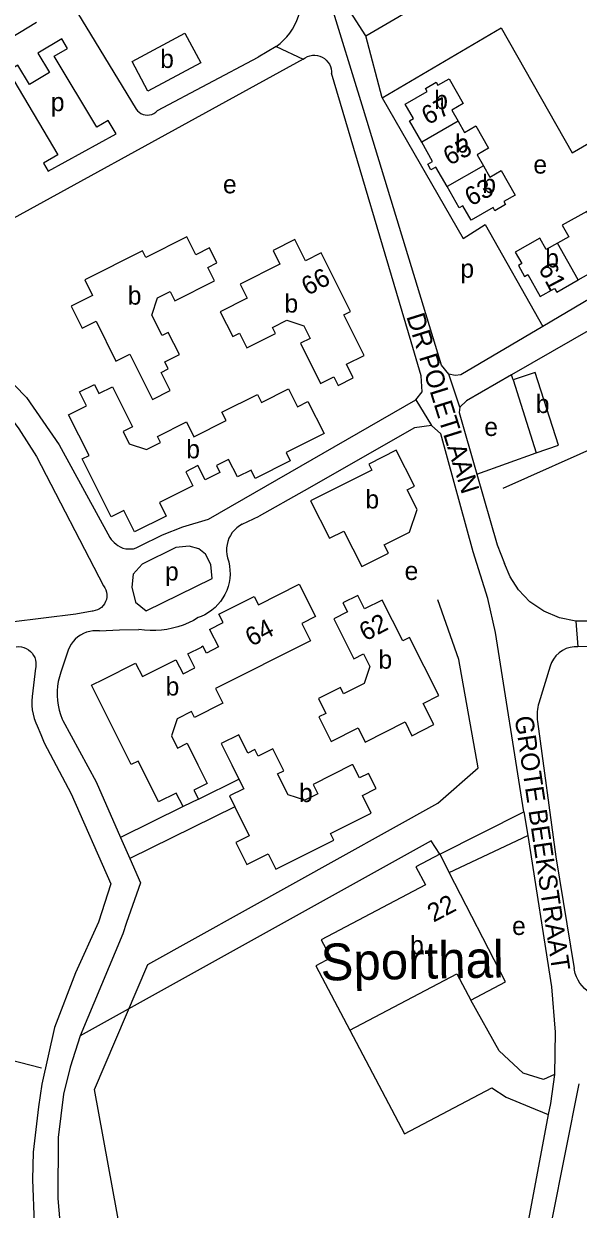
# Model space of a CAD drawing. Extents: x 158142 to 159655, y 385262 to 387204.
# Drawn here: x 158722.6 to 158843.1, y 386403.5 to 386661 of the extents above; entities that cross this region are included whole.
import ezdxf

# ---------------------------------------------------------------- set-up
doc = ezdxf.new("R2010")
doc.units = 0
for name, color, linetype in [('BLT_Basislijn', 7, 'Continuous'), ('BLT_Bebouwing', 7, 'Continuous'), ('BLT_Bebouwing_beschrifting', 7, 'Continuous'), ('BLT_Centroide', 7, 'Continuous'), ('BLT_Huisnummer', 7, 'Continuous'), ('BLT_Huisnummer_ tussenligend', 7, 'Continuous'), ('BLT_Onderverdeling_panden', 7, 'Continuous'), ('BLT_Straatnaam_verkleind', 7, 'Continuous'), ('BLT_Vlakafsluiter', 7, 'Continuous')]:
    doc.layers.add(name, color=color, linetype=linetype)

msp = doc.modelspace()

# ---------------------------------------------------------------- linework, layer by layer
at = {"layer": 'BLT_Basislijn'}
for p, q in [((158796.96, 386658.41), (158786.24, 386675.16)), ((158728.49, 386672.91), (158747.01, 386642.5)), ((158796.96, 386658.41), (158813.21, 386667.91)), ((158800.5, 386644.91), (158796.96, 386658.41)), ((158751.66, 386642.15), (158773.56, 386653.78)), ((158777.49, 386656.07), (158773.56, 386653.78)), ((158806.78, 386591.92), (158789.49, 386650.31)), ((158828.98, 386583.64), (158828.64, 386584.76)), ((158826.78, 386560.1), (158854.55, 386572.55)), ((158821.11, 386563.19), (158833.99, 386567.84)), ((158770.06, 386552.33), (158773.75, 386554.02)), ((158732.06, 386524.48), (158730.67, 386520.15)), ((158725.15, 386521.03), (158724.4, 386514.88)), ((158725.48, 386508.52), (158726.28, 386506.62)), ((158760.54, 386492.61), (158769.34, 386496.95)), ((158757.24, 386490.95), (158743.6, 386484.26)), ((158768.47, 386490.9), (158745.62, 386479.68)), ((158813.04, 386480.63), (158831.27, 386489.83)), ((158831.27, 386489.83), (158832.15, 386484.68)), ((158743.6, 386484.26), (158745.62, 386479.68)), ((158811.12, 386483.52), (158734.85, 386441.17)), ((158710.88, 386438.27), (158726.42, 386434.18))]:
    msp.add_line(p, q, dxfattribs=at)
for points in [[(158800.5, 386644.91), (158826.35, 386660.11), (158841.79, 386632.99), (158934.18, 386686.67), (158951.94, 386658.76)], [(158777.49, 386656.07), (158778.31, 386656.71), (158779.07, 386657.42), (158779.78, 386658.18), (158780.43, 386658.99), (158781.01, 386659.85), (158781.52, 386660.75), (158781.97, 386661.69), (158782.34, 386662.66), (158782.64, 386663.66), (158782.85, 386664.68), (158782.99, 386665.71), (158783.05, 386666.74), (158783.03, 386667.78), (158782.93, 386668.82), (158782.75, 386669.84), (158782.49, 386670.85), (158782.16, 386671.83), (158781.75, 386672.79), (158781.27, 386673.71), (158780.72, 386674.59), (158780.64, 386674.69)], [(158796.42, 386642.36), (158789, 386666.64)], [(158783.34, 386653.33), (158783.79, 386653.65), (158784.28, 386653.89), (158784.8, 386654.07), (158785.34, 386654.16), (158785.89, 386654.18), (158786.43, 386654.12), (158786.96, 386653.97), (158787.47, 386653.76), (158787.93, 386653.47), (158788.35, 386653.12), (158788.72, 386652.71), (158789.02, 386652.25), (158789.25, 386651.75), (158789.41, 386651.23), (158789.48, 386650.68), (158789.49, 386650.31)], [(158783.34, 386653.33), (158700.4, 386607.86), (158696.69, 386605.76)], [(158800.5, 386644.91), (158818.12, 386614.39), (158822.89, 386617.39), (158835.4, 386595.28)], [(158747.01, 386642.5), (158747.31, 386642.11), (158747.67, 386641.79), (158748.07, 386641.52), (158748.52, 386641.33), (158748.99, 386641.21), (158749.47, 386641.17), (158749.95, 386641.21), (158750.42, 386641.32), (158750.86, 386641.52), (158751.27, 386641.78), (158751.66, 386642.15)], [(158815.02, 386584.89), (158813.4, 386586.86), (158796.42, 386642.36)], [(158925.01, 386641.49), (158915.91, 386635.65), (158913.62, 386633.64), (158910.28, 386627.76), (158908.07, 386625.82), (158897.31, 386623.34), (158889.29, 386621.08), (158876.15, 386616.73), (158865.98, 386612.5), (158856.4, 386607.67), (158835.4, 386595.28)], [(158943.04, 386622.77), (158928.51, 386622.6), (158913, 386620.87), (158891.33, 386615.63), (158878.55, 386611.27), (158868.25, 386606.92), (158859.58, 386602.5), (158828.64, 386584.76)], [(158696.08, 386598.01), (158712.54, 386589.37), (158718.01, 386585.14), (158723.17, 386579.86), (158730.26, 386569.56), (158741.33, 386549.4)], [(158835.4, 386595.28), (158817.63, 386584.79), (158816.36, 386584.63), (158815.02, 386584.89)], [(158694.85, 386593.18), (158708.52, 386585.9), (158712.94, 386582.4), (158718.17, 386577.51), (158721.5, 386572.99), (158725.33, 386567.01), (158739.93, 386538.93)], [(158807.85, 386579.31), (158809.18, 386581.09), (158808.98, 386584.51), (158806.78, 386591.92)], [(158828.64, 386584.76), (158818.83, 386579.14), (158817.41, 386577.76)], [(158762.73, 386553.41), (158807.85, 386579.31)], [(158817.41, 386577.76), (158817.25, 386576.55), (158821.11, 386563.19)], [(158811.26, 386573.73), (158807.52, 386573.23), (158783.57, 386559.59), (158773.75, 386554.02)], [(158831.27, 386489.83), (158825.12, 386528.81), (158823.48, 386536.16), (158820.27, 386546.34), (158813.29, 386571.91), (158811.26, 386573.73)], [(158821.11, 386563.19), (158825.53, 386547.86), (158827.13, 386543.77)], [(158741.33, 386549.4), (158741.6, 386549), (158741.86, 386548.67), (158742.24, 386548.31), (158742.65, 386547.94), (158743.04, 386547.66), (158743.56, 386547.4), (158744.15, 386547.13), (158744.8, 386546.96), (158745.24, 386546.94), (158745.86, 386546.94), (158746.42, 386546.98), (158747.01, 386547.15), (158747.78, 386547.54), (158752.78, 386549.97), (158757.18, 386551.7), (158762.73, 386553.41)], [(158770.06, 386552.33), (158769.45, 386551.96), (158768.88, 386551.53), (158768.37, 386551.03), (158767.91, 386550.48), (158767.52, 386549.88), (158767.2, 386549.24), (158766.95, 386548.58), (158766.78, 386547.88), (158766.68, 386547.17), (158766.67, 386546.46), (158766.73, 386545.75), (158766.9, 386544.98)], [(158766.9, 386544.98), (158767.15, 386544.11), (158767.32, 386543.22), (158767.42, 386542.32), (158767.43, 386541.42), (158767.37, 386540.52), (158767.22, 386539.62), (158767, 386538.75), (158766.7, 386537.89), (158766.33, 386537.07), (158765.88, 386536.28), (158765.37, 386535.54), (158764.79, 386534.84), (158764.16, 386534.2), (158763.47, 386533.61), (158762.73, 386533.09), (158761.95, 386532.64), (158761.13, 386532.26), (158760.53, 386532.03)], [(158842.64, 386531.24), (158839.05, 386531.95), (158835.64, 386533.39), (158832.63, 386535.46), (158830.17, 386538.02), (158828.34, 386540.85), (158827.13, 386543.77)], [(158739.93, 386538.93), (158740.22, 386538.5), (158740.44, 386538.03), (158740.59, 386537.53), (158740.66, 386537.02), (158740.65, 386536.49), (158740.56, 386535.98), (158740.39, 386535.49), (158740.15, 386535.03), (158739.84, 386534.61), (158739.47, 386534.24), (158739.05, 386533.93), (158738.58, 386533.7), (158738.09, 386533.53), (158737.57, 386533.44), (158737.45, 386533.43)], [(158757.54, 386322.67), (158737.93, 386429.5), (158749.55, 386456.64), (158812.62, 386491.7), (158821.39, 386499.37), (158817.14, 386522.92), (158812.61, 386535.9)], [(158737.45, 386533.43), (158733.92, 386532.74), (158705.73, 386529.3)], [(158852.43, 386533.1), (158849.49, 386531.93), (158846.18, 386531.26), (158842.64, 386531.24)], [(158760.53, 386532.03), (158759.47, 386531.42), (158758.38, 386530.88), (158757.25, 386530.4), (158756.1, 386530.01), (158754.92, 386529.69), (158753.72, 386529.45), (158752.51, 386529.29), (158751.29, 386529.2), (158750.07, 386529.2), (158748.85, 386529.28), (158747.63, 386529.44)], [(158739.07, 386529.12), (158738.35, 386529.17), (158737.63, 386529.13), (158736.92, 386529.02), (158736.22, 386528.83), (158735.56, 386528.57), (158734.92, 386528.23), (158734.33, 386527.82), (158733.78, 386527.35), (158733.29, 386526.82), (158732.87, 386526.24), (158732.5, 386525.62), (158732.21, 386524.96), (158732.06, 386524.48)], [(158739.07, 386529.12), (158743.38, 386529.34), (158747.63, 386529.44)], [(158720.96, 386525.69), (158721.51, 386525.71), (158722.06, 386525.66), (158722.6, 386525.52), (158723.11, 386525.31), (158723.59, 386525.03), (158724.02, 386524.68), (158724.4, 386524.28), (158724.71, 386523.82), (158724.96, 386523.33), (158725.13, 386522.8), (158725.23, 386522.25), (158725.24, 386521.7), (158725.18, 386521.15), (158725.15, 386521.03)], [(158843.07, 386525.7), (158842.23, 386525.68), (158841.37, 386525.54), (158840.52, 386525.27), (158839.7, 386524.87), (158838.95, 386524.35), (158838.29, 386523.72), (158837.74, 386523.01), (158837.32, 386522.25), (158837.02, 386521.46)], [(158852.68, 386527.24), (158852.11, 386527), (158849.15, 386526.17), (158846.11, 386525.73), (158843.07, 386525.7)], [(158730.67, 386520.15), (158730.35, 386519.16), (158730.1, 386518.14), (158729.93, 386517.11), (158729.84, 386516.08), (158729.83, 386515.03), (158729.9, 386513.99), (158730.05, 386512.96), (158730.28, 386511.94), (158730.58, 386510.95), (158730.96, 386509.98), (158731.09, 386509.7)], [(158837.02, 386521.46), (158834.54, 386513.4)], [(158724.4, 386514.88), (158724.33, 386513.91), (158724.34, 386512.95), (158724.44, 386511.98), (158724.61, 386511.03), (158724.86, 386510.09), (158725.18, 386509.18), (158725.48, 386508.52)], [(158834.54, 386513.4), (158834.43, 386512.97), (158834.35, 386512.53), (158834.27, 386512.09), (158834.22, 386511.65), (158834.19, 386511.21), (158834.17, 386510.76), (158834.18, 386510.32), (158834.2, 386509.88), (158834.24, 386509.43)], [(158731.09, 386509.7), (158738.3, 386496.31), (158743.6, 386484.26)], [(158834.24, 386509.43), (158838.29, 386480.03), (158842.24, 386455.77)], [(158726.28, 386506.62), (158727, 386504.84), (158732.89, 386493.7), (158741.5, 386474.16), (158738.85, 386465.87), (158733.82, 386454.83), (158729.3, 386442.97), (158726.5, 386430.65), (158725.78, 386425.75), (158724.61, 386415.86), (158724.5, 386409.95), (158724.83, 386400.43), (158727.71, 386375.28), (158734.92, 386340.45), (158744.35, 386298.39), (158748.73, 386281.78), (158755.35, 386261.93), (158761.86, 386241.17)], [(158815.08, 386476.68), (158832.15, 386484.68)], [(158832.15, 386484.68), (158837.28, 386451.8), (158838.08, 386441.95), (158838, 386432.76)], [(158813.04, 386480.63), (158811.12, 386483.52)], [(158745.62, 386479.68), (158747.94, 386474.42), (158744.94, 386465.78), (158744.09, 386463.34), (158734.85, 386441.17)], [(158850.89, 386449.52), (158850.13, 386449.43), (158849.36, 386449.41), (158848.59, 386449.47), (158847.83, 386449.62), (158847.09, 386449.84), (158846.38, 386450.14), (158845.71, 386450.5), (158845.07, 386450.94), (158844.49, 386451.44), (158843.96, 386452), (158843.49, 386452.61), (158843.08, 386453.26), (158842.75, 386453.96), (158842.49, 386454.68), (158842.3, 386455.43), (158842.24, 386455.77)], [(158838, 386432.76), (158835.58, 386431.65), (158831.19, 386433.08), (158825.91, 386437.87), (158819.8, 386448.9)], [(158734.85, 386441.17), (158732.67, 386434.38), (158731.21, 386428.49), (158730.09, 386419.09), (158730.02, 386405.84), (158731.42, 386388.95), (158733.76, 386371.24), (158747.12, 386306.2), (158753.2, 386284.87), (158764.97, 386248.15)], [(158793.47, 386442.36), (158805.34, 386419.87), (158824.34, 386429.9), (158827.47, 386427.84), (158832.5, 386425.75), (158836.62, 386424.04)], [(158838, 386432.76), (158837.08, 386426.49), (158836.62, 386424.04)], [(158843.29, 386430.77), (158837.33, 386400.92), (158837.2, 386395.94), (158837.65, 386388.99), (158838.18, 386387.27)], [(158836.62, 386424.04), (158831.91, 386398.97), (158831.88, 386390.19)]]:
    msp.add_lwpolyline(points, dxfattribs=at)
for points in [[(158730.85, 386657.75), (158725.64, 386654.65), (158728.16, 386650.42), (158723.8, 386647.82), (158721.29, 386652.03), (158716.07, 386648.92), (158717.32, 386646.82), (158720.43, 386648.68), (158730.02, 386632.57), (158726.88, 386630.7), (158727.87, 386629.03), (158742.68, 386637.11), (158740.94, 386640.01), (158738.48, 386638.53), (158729.22, 386653.98), (158732.1, 386655.63)], [(158755.63, 386547.24), (158748.3, 386543.59), (158746.39, 386541.47), (158746.05, 386538.63), (158746.88, 386535.38), (158749.2, 386533.52), (158763.57, 386540.53), (158763.25, 386543.55), (158762.12, 386545.77), (158760.67, 386546.93), (158758.51, 386547.5)]]:
    msp.add_lwpolyline(points, close=True, dxfattribs=at)
at = {"layer": 'BLT_Bebouwing'}
for p, q in [((158828.98, 386583.64), (158833.99, 386567.84)), ((158760.54, 386492.61), (158757.24, 386490.95)), ((158813.04, 386480.63), (158815.08, 386476.68))]:
    msp.add_line(p, q, dxfattribs=at)
for points in [[(158725.33, 386661.29), (158717.94, 386656.78), (158716.61, 386658.87), (158715.3, 386658.1), (158713.66, 386658.48), (158708.76, 386655.49), (158708.35, 386653.84), (158707.05, 386653.03), (158708.34, 386650.9)], [(158805.52, 386643.57), (158810.28, 386646.29), (158809.89, 386646.99), (158812.24, 386648.33), (158812.63, 386647.65), (158815.07, 386649.05), (158818.14, 386643.66), (158815.65, 386642.24), (158817.03, 386639.83)], [(158809.09, 386635.3), (158806.44, 386639.95), (158807.3, 386640.44), (158805.52, 386643.57)], [(158817.03, 386639.83), (158818.4, 386637.41), (158820.87, 386638.82), (158823.62, 386633.99), (158821.13, 386632.57), (158822.51, 386630.14)], [(158814.6, 386625.63), (158812.18, 386629.89), (158811.11, 386629.29), (158810.43, 386630.5), (158811.48, 386631.1), (158809.09, 386635.3)], [(158822.51, 386630.14), (158823.89, 386627.71), (158826.39, 386629.13), (158829.42, 386623.81), (158826.96, 386622.42), (158827.35, 386621.74), (158824.99, 386620.4), (158824.6, 386621.09), (158819.82, 386618.36), (158818.03, 386621.5), (158817.22, 386621.04), (158814.6, 386625.63)], [(158843.11, 386605.37), (158847.77, 386608.01), (158847.3, 386608.84), (158850.48, 386610.64), (158847.77, 386615.42), (158848.36, 386615.75), (158847.03, 386618.11), (158846.41, 386617.75), (158844.99, 386620.25), (158839.65, 386617.23), (158841.07, 386614.72), (158838.6, 386613.33)], [(158735.83, 386605.42), (158737.54, 386602.01), (158732.91, 386599.69), (158735.31, 386594.89), (158738.29, 386596.39), (158742.63, 386587.74), (158745.62, 386589.24), (158750.54, 386579.42), (158754.44, 386581.37), (158752.49, 386585.27), (158754, 386586.03), (158753.23, 386587.56), (158756.42, 386589.16), (158754, 386593.98), (158752.65, 386593.3), (158750.42, 386597.74), (158751.67, 386601.49), (158754.42, 386602.86), (158755.43, 386600.86), (158764.08, 386605.19), (158762.62, 386608.1), (158764.58, 386609.08), (158762.96, 386612.33), (158759.96, 386610.82), (158758.01, 386614.71), (158749.13, 386610.27), (158748.4, 386611.72), (158735.83, 386605.42)], [(158776.78, 386611.74), (158778.25, 386608.8), (158769.61, 386604.47), (158771.16, 386601.39), (158765.3, 386598.46), (158768.01, 386593.05), (158769.48, 386593.79), (158771.07, 386590.62), (158777.29, 386593.73), (158776.63, 386595.05), (158779.79, 386596.63), (158783.45, 386595.42), (158784.82, 386592.68), (158782.73, 386591.63), (158787.12, 386582.89), (158789.97, 386584.32), (158790.91, 386582.46), (158794.21, 386584.11), (158792.74, 386587.04), (158796.58, 386588.96), (158792.15, 386597.79), (158793.6, 386598.52), (158787.23, 386611.22), (158783.85, 386609.52), (158781.54, 386614.12), (158776.78, 386611.74)], [(158838.6, 386613.33), (158836.17, 386611.95), (158834.77, 386614.42), (158829.43, 386611.4), (158830.84, 386608.92), (158830.13, 386608.52), (158831.47, 386606.15)], [(158831.47, 386606.15), (158832.18, 386606.55), (158834.88, 386601.77), (158837.99, 386603.53), (158838.44, 386602.73), (158843.11, 386605.37)], [(158833.99, 386567.84), (158838.83, 386569.44), (158833.75, 386585.29), (158828.98, 386583.64)], [(158765.19, 386563.57), (158761.99, 386561.96), (158760.45, 386565.03), (158757.79, 386563.7), (158759.32, 386560.63), (158752.08, 386557), (158753.55, 386554.07), (158746.67, 386550.62), (158744.33, 386555.29), (158741.61, 386553.92), (158735.31, 386566.49), (158736.78, 386567.22), (158732.33, 386576.1), (158736.2, 386578.04), (158734.71, 386581.03), (158737.93, 386582.65), (158738.92, 386580.68), (158741.86, 386582.15), (158746.2, 386573.49), (158744.17, 386572.47), (158745.52, 386569.77), (158749.28, 386568.52), (158752.34, 386570.05), (158751.67, 386571.39), (158757.93, 386574.53), (158759.56, 386571.29), (158766.58, 386574.81), (158765.67, 386576.62), (158773.39, 386580.49), (158774.25, 386578.76), (158780.14, 386581.71), (158782.09, 386577.82), (158784.37, 386578.96), (158787.86, 386572), (158779.62, 386567.87), (158780.53, 386566.07), (158772.9, 386562.24), (158771.99, 386564.05), (158769.03, 386562.57), (158767.12, 386566.37), (158764.46, 386565.04), (158765.19, 386563.57)], [(158808.1, 386555.48), (158805.94, 386559.78), (158807.5, 386560.55), (158803.58, 386568.36), (158797.57, 386565.35), (158798.24, 386564.02), (158784.95, 386557.35), (158789.02, 386549.24), (158792.17, 386550.82), (158796.05, 386543.1), (158801.86, 386546.02), (158800.96, 386547.81), (158806.47, 386550.57), (158808.1, 386555.48)], [(158762.99, 386529.46), (158765.91, 386530.92), (158765, 386532.74), (158772.7, 386536.61), (158773.61, 386534.8), (158782.47, 386539.25), (158785.99, 386532.24), (158783.01, 386530.74), (158784.91, 386526.96), (158764.29, 386516.61), (158765.88, 386513.43), (158759.69, 386510.33), (158759.05, 386511.6), (158755.94, 386510.04), (158754.71, 386506.32), (158756.03, 386503.69), (158758.09, 386504.73), (158760.46, 386500), (158762.48, 386496), (158759.57, 386494.54), (158760.54, 386492.61)], [(158791.97, 386535.21), (158792.96, 386533.24), (158790, 386531.75), (158794.36, 386523.07), (158796.44, 386524.12), (158797.81, 386521.39), (158796.59, 386517.72), (158792.09, 386515.46), (158791.41, 386516.81), (158786.63, 386514.41), (158788.23, 386511.22), (158786.73, 386510.47), (158789.43, 386505.09), (158795.31, 386508.04), (158796.84, 386504.99), (158805.49, 386509.34), (158806.98, 386506.36), (158811.76, 386508.76), (158809.43, 386513.39), (158812.79, 386515.08), (158806.46, 386527.69), (158804.99, 386526.95), (158800.53, 386535.82), (158796.68, 386533.89), (158795.2, 386536.83), (158791.97, 386535.21)], [(158762.99, 386529.46), (158764.9, 386525.64), (158762.28, 386524.32), (158761.55, 386525.78), (158761.21, 386525.61)], [(158757.24, 386490.95), (158755.75, 386493.91), (158751.9, 386491.97), (158747.87, 386500), (158747.44, 386500.84), (158745.97, 386500.1), (158739.64, 386512.72), (158737.33, 386517.32), (158740.02, 386518.67), (158746.9, 386522.13), (158748.37, 386519.19), (158755.67, 386522.86), (158757.21, 386519.78), (158759.8, 386521.07), (158758.27, 386524.13), (158761.21, 386525.61)], [(158794.14, 386500), (158793.93, 386500), (158785.47, 386495.75), (158786.49, 386493.72), (158783.72, 386492.33), (158780.04, 386493.55), (158777.77, 386498.07), (158779.12, 386498.75), (158778.49, 386500), (158776.73, 386503.5), (158773.57, 386501.91), (158772.84, 386503.37), (158771.3, 386502.6), (158769.31, 386506.56), (158765.48, 386504.64), (158767.81, 386500), (158769.34, 386496.95)], [(158768.47, 386490.9), (158771.62, 386484.62), (158768.72, 386483.16), (158771.11, 386478.41), (158775.72, 386480.72), (158777.42, 386477.34), (158790.01, 386483.66), (158789.28, 386485.12), (158798.13, 386489.56), (158796.21, 386493.39), (158799.19, 386494.89), (158797.55, 386498.18), (158795.56, 386497.18), (158794.14, 386500)], [(158769.34, 386496.95), (158770.4, 386494.84), (158767.28, 386493.27), (158768.47, 386490.9)], [(158813.04, 386480.63), (158807.84, 386477.9), (158809.92, 386473.95), (158787.27, 386461.99), (158789.31, 386458.12), (158786.06, 386456.4), (158793.47, 386442.36)], [(158819.8, 386448.9), (158827.31, 386452.93), (158815.08, 386476.68)], [(158793.47, 386442.36), (158816.76, 386454.66), (158819.8, 386448.9)]]:
    msp.add_lwpolyline(points, dxfattribs=at)
msp.add_lwpolyline([(158746.15, 386652.84), (158757.6, 386658.99), (158761.05, 386652.55), (158749.58, 386646.36)], close=True, dxfattribs=at)
at = {"layer": 'BLT_Onderverdeling_panden'}
for p, q in [((158817.03, 386639.83), (158809.09, 386635.3)), ((158822.51, 386630.14), (158814.6, 386625.63)), ((158843.11, 386605.37), (158838.6, 386613.33))]:
    msp.add_line(p, q, dxfattribs=at)
at = {"layer": 'BLT_Vlakafsluiter'}
for p, q in [((158777.49, 386656.07), (158783.34, 386653.33)), ((158817.41, 386577.76), (158815.02, 386584.89)), ((158807.85, 386579.31), (158811.26, 386573.73)), ((158842.64, 386531.24), (158843.07, 386525.7))]:
    msp.add_line(p, q, dxfattribs=at)

# ---------------------------------------------------------------- texts
at = {"layer": 'BLT_Bebouwing_beschrifting'}
msp.add_text('Sporthal', height=8, rotation=1, dxfattribs=at).set_placement((158787.18, 386453.16))
at = {"layer": 'BLT_Centroide'}
for s, p in [('b', (158752.25, 386651.42)), ('b', (158811.83, 386642.48)), ('p', (158728.47, 386642.03)), ('b', (158816.36, 386633.03)), ('e', (158833.38, 386628.47)), ('b', (158822.28, 386624.25)), ('e', (158765.9, 386624.18)), ('b', (158835.97, 386608.09)), ('p', (158817.52, 386605.85)), ('b', (158745.19, 386600)), ('b', (158779.27, 386598.28)), ('b', (158833.91, 386576.45)), ('e', (158822.71, 386571.47)), ('b', (158757.92, 386566.62)), ('b', (158796.87, 386555.72)), ('p', (158753.3, 386540.07)), ('e', (158805.38, 386540.19)), ('b', (158799.7, 386520.92)), ('b', (158753.43, 386515.09)), ('b', (158782.44, 386491.94)), ('e', (158828.75, 386463.07)), ('b', (158806.59, 386458.88))]:
    msp.add_text(s, height=4, dxfattribs=at).set_placement(p)
at = {"layer": 'BLT_Huisnummer'}
for s, rotation, p in [('67', 27.8253, (158810.41, 386638.95)), ('63', 27.8253, (158819.8, 386621.29)), ('66', 27.8253, (158784.29, 386601.87)), ('61', 297.8252, (158834.37, 386607.89)), ('62', 27.8253, (158796.86, 386526.79)), ('64', 27.8253, (158772.08, 386525.64)), ('22', 27.8253, (158811.67, 386465.74))]:
    msp.add_text(s, height=4, rotation=rotation, dxfattribs=at).set_placement(p)
at = {"layer": 'BLT_Huisnummer_ tussenligend'}
msp.add_text('65', height=4, rotation=27.8253, dxfattribs=at).set_placement((158815.13, 386630.13))
at = {"layer": 'BLT_Straatnaam_verkleind'}
for s, rotation, p in [('DR POLETLAAN', 287.407, (158805.72, 386597.45)), ('GROTE BEEKSTRAAT', 278.407, (158829.29, 386510.39))]:
    msp.add_text(s, height=4, rotation=rotation, dxfattribs=at).set_placement(p)

doc.saveas('drawing.dxf')
